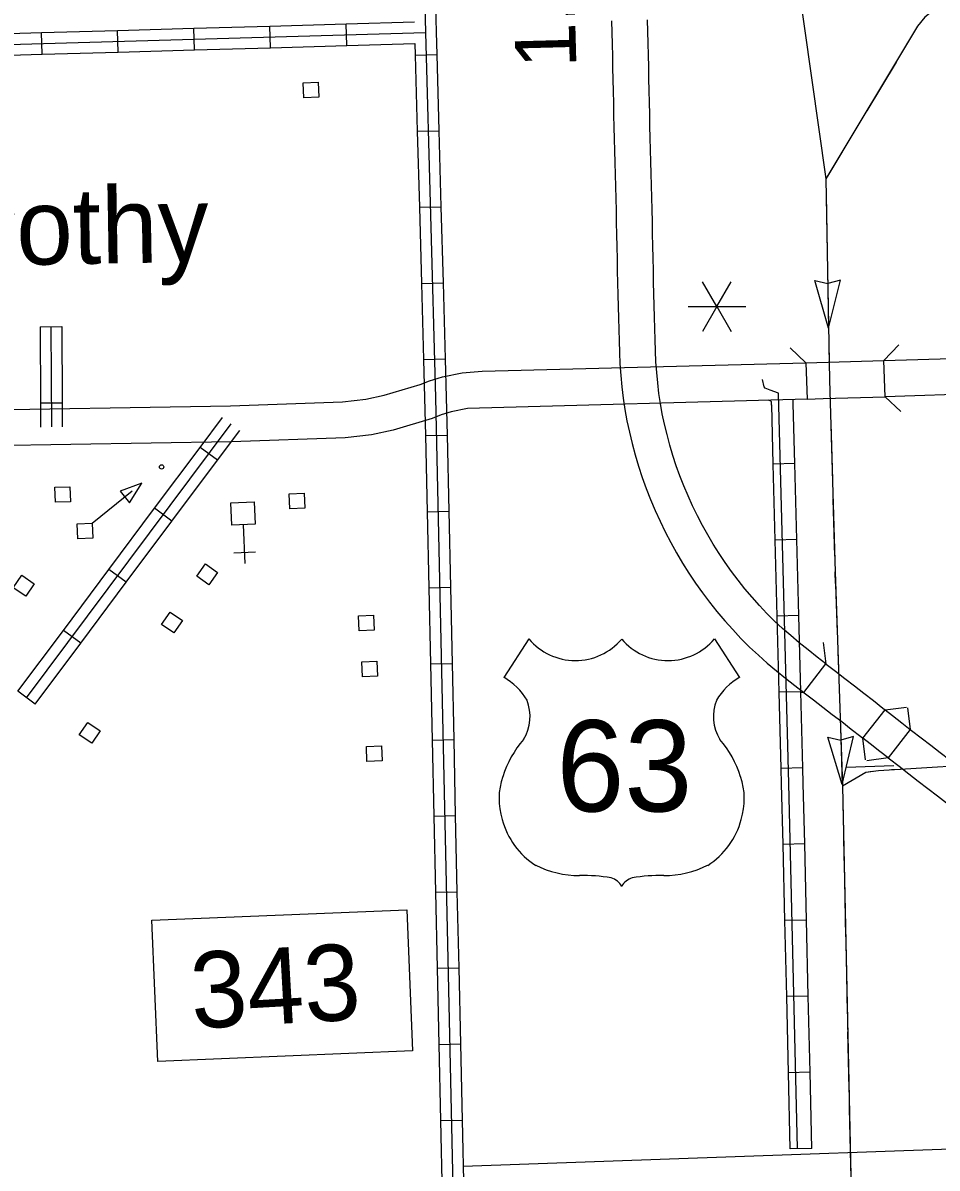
# Model space of a CAD drawing. Extents: x 1671357 to 13005564, y 567358 to 14261451.
# Drawn here: x 12758262.26 to 12758274.26, y 14259885.6 to 14259900.64 of the extents above; entities that cross this region are included whole.
import ezdxf

# ---------------------------------------------------------------- set-up
doc = ezdxf.new("R2010")
doc.units = 0
for name, color, linetype in [('10', 7, 'Continuous'), ('15', 7, 'Continuous'), ('22', 7, 'Continuous'), ('24', 7, 'Continuous'), ('32', 7, 'Continuous'), ('35', 7, 'Continuous'), ('37', 7, 'Continuous'), ('43', 7, 'Continuous'), ('48', 7, 'Continuous'), ('5', 7, 'Continuous'), ('56', 7, 'Continuous'), ('6', 7, 'Continuous'), ('60', 7, 'Continuous')]:
    doc.layers.add(name, color=color, linetype=linetype)

msp = doc.modelspace()

# ---------------------------------------------------------------- linework, layer by layer
at = {"layer": '10'}
msp.add_line((12758273.563, 14259896.205), (12758276.117, 14259896.288), dxfattribs=at)
msp.add_lwpolyline([(12758252.103, 14259895.45), (12758257.601, 14259895.49), (12758264.985, 14259895.609), (12758266.455, 14259895.665), (12758266.759, 14259895.697), (12758266.999, 14259895.749), (12758267.474, 14259895.892), (12758267.595, 14259895.941), (12758267.766, 14259895.99), (12758268.026, 14259896.045), (12758268.289, 14259896.068), (12758272.536, 14259896.175), (12758272.553, 14259895.7), (12758268.096, 14259895.575), (12758267.879, 14259895.53), (12758267.75, 14259895.493), (12758267.633, 14259895.445), (12758267.117, 14259895.291), (12758266.835, 14259895.229), (12758266.49, 14259895.192), (12758264.998, 14259895.136), (12758257.606, 14259895.017), (12758252.112, 14259894.977)], close=True, dxfattribs=at)
for points in [[(12758272.539, 14259896.175), (12758273.563, 14259896.205)], [(12758276.286, 14259895.828), (12758276.18, 14259895.817), (12758273.578, 14259895.731), (12758273.563, 14259896.205)], [(12758272.553, 14259895.7), (12758272.763, 14259895.705), (12758273.578, 14259895.731)]]:
    msp.add_lwpolyline(points, dxfattribs=at)
at = {"layer": '15'}
for p, q in [((12758272.513, 14259891.845), (12758272.802, 14259892.22)), ((12758273.287, 14259891.244), (12758273.579, 14259891.616)), ((12758273.909, 14259891.359), (12758273.62, 14259890.984))]:
    msp.add_line(p, q, dxfattribs=at)
for points in [[(12758269.985, 14259900.671), (12758269.989, 14259900.516), (12758269.993, 14259900.361), (12758269.997, 14259900.207)], [(12758270.471, 14259900.219), (12758270.467, 14259900.374), (12758270.462, 14259900.529), (12758270.458, 14259900.684)], [(12758269.997, 14259900.208), (12758270.001, 14259900.053), (12758270.004, 14259899.899), (12758270.007, 14259899.743), (12758270.011, 14259899.587), (12758270.014, 14259899.431), (12758270.018, 14259899.274), (12758270.022, 14259899.118), (12758270.026, 14259898.962), (12758270.031, 14259898.806), (12758270.035, 14259898.649), (12758270.039, 14259898.493), (12758270.042, 14259898.337), (12758270.045, 14259898.179), (12758270.049, 14259898.02), (12758270.053, 14259897.861), (12758270.056, 14259897.701), (12758270.059, 14259897.542), (12758270.062, 14259897.384), (12758270.066, 14259897.226), (12758270.069, 14259897.07), (12758270.072, 14259896.916), (12758270.076, 14259896.764), (12758270.08, 14259896.613), (12758270.085, 14259896.463), (12758270.091, 14259896.313), (12758270.097, 14259896.162), (12758270.108, 14259896.011), (12758270.122, 14259895.861), (12758270.14, 14259895.712), (12758270.161, 14259895.563), (12758270.189, 14259895.414), (12758270.221, 14259895.266), (12758270.256, 14259895.117), (12758270.296, 14259894.967), (12758270.34, 14259894.818), (12758270.388, 14259894.67), (12758270.441, 14259894.523), (12758270.498, 14259894.378), (12758270.558, 14259894.235), (12758270.623, 14259894.094), (12758270.691, 14259893.954), (12758270.763, 14259893.816), (12758270.839, 14259893.679), (12758270.918, 14259893.545), (12758271.001, 14259893.412), (12758271.088, 14259893.282), (12758271.179, 14259893.155), (12758271.274, 14259893.03), (12758271.371, 14259892.908), (12758271.473, 14259892.787), (12758271.577, 14259892.67), (12758271.686, 14259892.555), (12758271.798, 14259892.442), (12758271.914, 14259892.334), (12758272.031, 14259892.231), (12758272.151, 14259892.131), (12758272.272, 14259892.033), (12758272.394, 14259891.937), (12758272.513, 14259891.845)], [(12758272.802, 14259892.22), (12758272.685, 14259892.31), (12758272.567, 14259892.403), (12758272.452, 14259892.496), (12758272.34, 14259892.591), (12758272.231, 14259892.686), (12758272.127, 14259892.783), (12758272.026, 14259892.884), (12758271.927, 14259892.989), (12758271.831, 14259893.097), (12758271.738, 14259893.208), (12758271.648, 14259893.321), (12758271.561, 14259893.435), (12758271.478, 14259893.552), (12758271.398, 14259893.67), (12758271.322, 14259893.791), (12758271.25, 14259893.914), (12758271.18, 14259894.04), (12758271.114, 14259894.167), (12758271.051, 14259894.296), (12758270.992, 14259894.427), (12758270.936, 14259894.558), (12758270.884, 14259894.69), (12758270.836, 14259894.823), (12758270.792, 14259894.959), (12758270.752, 14259895.095), (12758270.715, 14259895.232), (12758270.682, 14259895.37), (12758270.653, 14259895.506), (12758270.629, 14259895.64), (12758270.609, 14259895.774), (12758270.593, 14259895.911), (12758270.58, 14259896.05), (12758270.57, 14259896.189), (12758270.564, 14259896.332), (12758270.558, 14259896.478), (12758270.554, 14259896.627), (12758270.55, 14259896.776), (12758270.546, 14259896.927), (12758270.542, 14259897.081), (12758270.539, 14259897.236), (12758270.536, 14259897.393), (12758270.532, 14259897.552), (12758270.529, 14259897.711), (12758270.526, 14259897.871), (12758270.523, 14259898.03), (12758270.519, 14259898.189), (12758270.516, 14259898.347), (12758270.512, 14259898.505), (12758270.508, 14259898.662), (12758270.504, 14259898.818), (12758270.5, 14259898.975), (12758270.495, 14259899.131), (12758270.491, 14259899.286), (12758270.488, 14259899.441), (12758270.484, 14259899.597), (12758270.481, 14259899.753), (12758270.478, 14259899.909), (12758270.474, 14259900.064), (12758270.471, 14259900.219)], [(12758272.802, 14259892.22), (12758272.805, 14259892.217), (12758272.928, 14259892.123), (12758273.051, 14259892.027), (12758273.175, 14259891.931), (12758273.3, 14259891.834), (12758273.426, 14259891.737), (12758273.55, 14259891.639), (12758273.579, 14259891.616)], [(12758272.513, 14259891.845), (12758272.516, 14259891.842), (12758272.639, 14259891.748), (12758272.762, 14259891.653), (12758272.885, 14259891.557), (12758273.009, 14259891.461), (12758273.134, 14259891.364), (12758273.258, 14259891.266), (12758273.287, 14259891.244)], [(12758273.579, 14259891.616), (12758273.675, 14259891.541), (12758273.8, 14259891.444), (12758273.909, 14259891.359)], [(12758273.909, 14259891.359), (12758273.925, 14259891.347), (12758274.052, 14259891.249), (12758274.178, 14259891.152), (12758274.303, 14259891.055), (12758274.429, 14259890.958), (12758274.555, 14259890.861), (12758274.674, 14259890.769)], [(12758273.62, 14259890.984), (12758273.509, 14259891.07), (12758273.383, 14259891.168), (12758273.287, 14259891.244)], [(12758273.62, 14259890.984), (12758273.636, 14259890.972), (12758273.762, 14259890.875), (12758273.888, 14259890.777), (12758274.014, 14259890.679), (12758274.14, 14259890.582), (12758274.266, 14259890.486), (12758274.385, 14259890.394)]]:
    msp.add_lwpolyline(points, dxfattribs=at)
at = {"layer": '22'}
for p, q in [((12758268.901, 14259892.549), (12758268.573, 14259892.042)), ((12758271.339, 14259892.549), (12758271.666, 14259892.042))]:
    msp.add_line(p, q, dxfattribs=at)
for centre, radius, start, end in [((12758269.511, 14259893.062), 0.798, 220.075, 319.6701), ((12758270.728, 14259893.062), 0.798, 220.3299, 319.925), ((12758268.145, 14259891.306), 0.852, 30.7809, 59.9883), ((12758272.095, 14259891.306), 0.852, 120.0117, 149.2191), ((12758268.332, 14259891.53), 0.584, 328.8105, 21.2108), ((12758271.907, 14259891.53), 0.584, 158.7892, 211.1895), ((12758269.859, 14259890.333), 1.362, 138.9565, 162.6913), ((12758270.38, 14259890.333), 1.362, 17.3087, 41.0435), ((12758269.409, 14259890.445), 0.9, 160.9576, 197.3819), ((12758270.83, 14259890.445), 0.9, 342.6181, 19.0424), ((12758269.556, 14259890.448), 1.042, 195.1074, 237.1312), ((12758270.684, 14259890.448), 1.042, 302.8688, 344.8926), ((12758269.575, 14259890.776), 1.337, 244.0771, 269.5779), ((12758270.664, 14259890.776), 1.337, 270.4221, 295.9229), ((12758269.606, 14259886.989), 2.45, 81.1942, 90.9539), ((12758269.913, 14259889.185), 0.235, 28.0342, 72.9864), ((12758270.327, 14259889.185), 0.235, 107.0136, 151.9658), ((12758270.633, 14259886.989), 2.45, 89.0461, 98.8058)]:
    msp.add_arc(centre, radius, start, end, dxfattribs=at)
at = {"layer": '32'}
for p, q in [((12758262.51, 14259900.231), (12758262.502, 14259900.515)), ((12758263.509, 14259900.259), (12758263.501, 14259900.543)), ((12758264.509, 14259900.288), (12758264.501, 14259900.572)), ((12758265.509, 14259900.316), (12758265.501, 14259900.6)), ((12758266.509, 14259900.345), (12758266.5, 14259900.629)), ((12758267.408, 14259900.218), (12758267.692, 14259900.226)), ((12758267.435, 14259899.218), (12758267.719, 14259899.226)), ((12758267.463, 14259898.219), (12758267.747, 14259898.226)), ((12758267.49, 14259897.219), (12758267.774, 14259897.227)), ((12758262.483, 14259896.65), (12758262.767, 14259896.651)), ((12758267.517, 14259896.219), (12758267.801, 14259896.227)), ((12758262.489, 14259895.65), (12758262.773, 14259895.651)), ((12758267.542, 14259895.22), (12758267.826, 14259895.226)), ((12758264.812, 14259894.895), (12758264.584, 14259895.065)), ((12758272.393, 14259894.854), (12758272.109, 14259894.846)), ((12758264.213, 14259894.094), (12758263.986, 14259894.264)), ((12758267.564, 14259894.22), (12758267.848, 14259894.226)), ((12758272.42, 14259893.854), (12758272.136, 14259893.846)), ((12758263.615, 14259893.292), (12758263.387, 14259893.462)), ((12758267.586, 14259893.22), (12758267.87, 14259893.226)), ((12758272.446, 14259892.854), (12758272.162, 14259892.847)), ((12758263.017, 14259892.491), (12758262.789, 14259892.661)), ((12758267.607, 14259892.22), (12758267.892, 14259892.227)), ((12758262.418, 14259891.69), (12758262.191, 14259891.86)), ((12758272.472, 14259891.854), (12758272.188, 14259891.847)), ((12758267.629, 14259891.22), (12758267.914, 14259891.227)), ((12758272.499, 14259890.855), (12758272.215, 14259890.847)), ((12758267.651, 14259890.221), (12758267.935, 14259890.227)), ((12758272.523, 14259889.854), (12758272.239, 14259889.848)), ((12758267.673, 14259889.221), (12758267.957, 14259889.227)), ((12758272.547, 14259888.854), (12758272.263, 14259888.848)), ((12758267.695, 14259888.221), (12758267.979, 14259888.227)), ((12758272.57, 14259887.855), (12758272.286, 14259887.848)), ((12758267.717, 14259887.221), (12758268.001, 14259887.227)), ((12758272.594, 14259886.855), (12758272.31, 14259886.848)), ((12758267.739, 14259886.221), (12758268.023, 14259886.227)), ((12758272.617, 14259885.855), (12758272.333, 14259885.848))]:
    msp.add_line(p, q, dxfattribs=at)
for points in [[(12758267.288, 14259909.193), (12758267.414, 14259905.851), (12758267.542, 14259900.517), (12758267.673, 14259895.717), (12758268.01, 14259880.366), (12758268.077, 14259880.309), (12758268.233, 14259880.297), (12758271.521, 14259880.629), (12758271.944, 14259880.629), (12758273.2, 14259880.673), (12758277.616, 14259880.857), (12758278.42, 14259880.876), (12758279.182, 14259880.918), (12758280.012, 14259880.961), (12758281.634, 14259881.05), (12758282.293, 14259881.066), (12758282.979, 14259881.061), (12758283.543, 14259881.078), (12758284.212, 14259881.201)], [(12758267.667, 14259901.225), (12758267.684, 14259900.521), (12758267.692, 14259900.226)], [(12758257.507, 14259900.229), (12758267.542, 14259900.517)], [(12758261.502, 14259900.486), (12758262.502, 14259900.515)], [(12758262.502, 14259900.515), (12758263.501, 14259900.543)], [(12758263.501, 14259900.543), (12758264.501, 14259900.572)], [(12758264.501, 14259900.572), (12758265.501, 14259900.6)], [(12758265.501, 14259900.6), (12758266.5, 14259900.629)], [(12758266.5, 14259900.629), (12758267.397, 14259900.655)], [(12758266.509, 14259900.345), (12758267.404, 14259900.371)], [(12758267.404, 14259900.371), (12758267.408, 14259900.218)], [(12758261.51, 14259900.202), (12758262.51, 14259900.231)], [(12758262.51, 14259900.231), (12758263.509, 14259900.259)], [(12758263.509, 14259900.259), (12758264.509, 14259900.288)], [(12758264.509, 14259900.288), (12758265.509, 14259900.316)], [(12758265.509, 14259900.316), (12758266.509, 14259900.345)], [(12758267.408, 14259900.218), (12758267.435, 14259899.218)], [(12758267.692, 14259900.226), (12758267.719, 14259899.226)], [(12758267.435, 14259899.218), (12758267.463, 14259898.219)], [(12758267.719, 14259899.226), (12758267.747, 14259898.226)], [(12758267.463, 14259898.219), (12758267.49, 14259897.219)], [(12758267.747, 14259898.226), (12758267.774, 14259897.227)], [(12758267.49, 14259897.219), (12758267.517, 14259896.219)], [(12758267.774, 14259897.227), (12758267.801, 14259896.227)], [(12758262.483, 14259896.65), (12758262.489, 14259895.65)], [(12758262.625, 14259896.65), (12758262.632, 14259895.333)], [(12758262.767, 14259896.651), (12758262.773, 14259895.651)], [(12758267.517, 14259896.219), (12758267.531, 14259895.714), (12758267.542, 14259895.22)], [(12758267.801, 14259896.227), (12758267.815, 14259895.721), (12758267.826, 14259895.226)], [(12758272.426, 14259885.854), (12758272.313, 14259890.648), (12758272.178, 14259895.777), (12758272.068, 14259895.817), (12758272.005, 14259895.845), (12758271.991, 14259895.86), (12758271.97, 14259895.956)], [(12758262.489, 14259895.65), (12758262.49, 14259895.332)], [(12758262.773, 14259895.651), (12758262.774, 14259895.334)], [(12758272.086, 14259895.668), (12758272.047, 14259895.685)], [(12758272.087, 14259895.62), (12758272.086, 14259895.668)], [(12758272.109, 14259894.846), (12758272.089, 14259895.625)], [(12758272.373, 14259895.638), (12758272.372, 14259895.69)], [(12758272.393, 14259894.854), (12758272.373, 14259895.639)], [(12758264.584, 14259895.065), (12758264.877, 14259895.458)], [(12758262.304, 14259891.775), (12758264.991, 14259895.373)], [(12758264.812, 14259894.895), (12758265.105, 14259895.288)], [(12758267.542, 14259895.22), (12758267.564, 14259894.22)], [(12758267.826, 14259895.226), (12758267.848, 14259894.226)], [(12758263.986, 14259894.264), (12758264.584, 14259895.065)], [(12758264.213, 14259894.094), (12758264.812, 14259894.895)], [(12758272.136, 14259893.846), (12758272.109, 14259894.846)], [(12758272.42, 14259893.854), (12758272.393, 14259894.854)], [(12758263.387, 14259893.462), (12758263.986, 14259894.264)], [(12758267.564, 14259894.22), (12758267.586, 14259893.22)], [(12758267.848, 14259894.226), (12758267.87, 14259893.226)], [(12758263.615, 14259893.292), (12758264.213, 14259894.094)], [(12758272.162, 14259892.847), (12758272.136, 14259893.846)], [(12758272.446, 14259892.854), (12758272.42, 14259893.854)], [(12758262.789, 14259892.661), (12758263.387, 14259893.462)], [(12758263.017, 14259892.491), (12758263.615, 14259893.292)], [(12758267.586, 14259893.22), (12758267.607, 14259892.22)], [(12758267.87, 14259893.226), (12758267.892, 14259892.227)], [(12758272.188, 14259891.847), (12758272.162, 14259892.847)], [(12758272.472, 14259891.854), (12758272.446, 14259892.854)], [(12758262.191, 14259891.86), (12758262.789, 14259892.661)], [(12758262.418, 14259891.69), (12758263.017, 14259892.491)], [(12758267.607, 14259892.22), (12758267.629, 14259891.22)], [(12758267.892, 14259892.227), (12758267.914, 14259891.227)], [(12758272.215, 14259890.847), (12758272.188, 14259891.847)], [(12758272.499, 14259890.855), (12758272.472, 14259891.854)], [(12758267.629, 14259891.22), (12758267.651, 14259890.221)], [(12758267.914, 14259891.227), (12758267.935, 14259890.227)], [(12758272.239, 14259889.848), (12758272.22, 14259890.643), (12758272.215, 14259890.847)], [(12758272.523, 14259889.854), (12758272.504, 14259890.65), (12758272.499, 14259890.855)], [(12758267.651, 14259890.221), (12758267.673, 14259889.221)], [(12758267.935, 14259890.227), (12758267.957, 14259889.227)], [(12758272.263, 14259888.848), (12758272.239, 14259889.848)], [(12758272.547, 14259888.854), (12758272.523, 14259889.854)], [(12758267.957, 14259889.227), (12758267.979, 14259888.227)], [(12758267.673, 14259889.221), (12758267.695, 14259888.221)], [(12758272.286, 14259887.848), (12758272.263, 14259888.848)], [(12758272.57, 14259887.855), (12758272.547, 14259888.854)], [(12758267.695, 14259888.221), (12758267.717, 14259887.221)], [(12758267.979, 14259888.227), (12758268.001, 14259887.227)], [(12758272.31, 14259886.848), (12758272.286, 14259887.848)], [(12758272.594, 14259886.855), (12758272.57, 14259887.855)], [(12758267.717, 14259887.221), (12758267.739, 14259886.221)], [(12758268.001, 14259887.227), (12758268.023, 14259886.227)], [(12758272.333, 14259885.848), (12758272.31, 14259886.848)], [(12758272.617, 14259885.855), (12758272.594, 14259886.855)], [(12758267.739, 14259886.221), (12758267.761, 14259885.221)], [(12758268.023, 14259886.227), (12758268.045, 14259885.227)]]:
    msp.add_lwpolyline(points, dxfattribs=at)
at = {"layer": '35'}
for points in [[(12758274.965, 14259901.018), (12758274.58, 14259900.927), (12758274.293, 14259900.832), (12758274.185, 14259900.783), (12758274.099, 14259900.717), (12758274.003, 14259900.601), (12758272.802, 14259898.593)], [(12758272.802, 14259898.593), (12758272.849, 14259895.95), (12758272.922, 14259893.429), (12758273.017, 14259890.615), (12758273.176, 14259883.241), (12758273.139, 14259882.897), (12758272.96, 14259882.398), (12758272.863, 14259882.216), (12758269.17, 14259876.344), (12758268.93, 14259876.062), (12758268.737, 14259875.922), (12758268.514, 14259875.793), (12758268.328, 14259875.705), (12758266.458, 14259875.091), (12758266.017, 14259874.983), (12758263.985, 14259874.814), (12758263.423, 14259874.758), (12758263.214, 14259874.724), (12758263.048, 14259874.668), (12758262.636, 14259874.462), (12758262.186, 14259874.219), (12758258.133, 14259871.914)]]:
    msp.add_lwpolyline(points, dxfattribs=at)
at = {"layer": '37'}
msp.add_line((12758273.571, 14259895.968), (12758273.571, 14259895.968), dxfattribs=at)
for points in [[(12758272.536, 14259896.175), (12758272.33, 14259896.371)], [(12758273.758, 14259896.412), (12758273.563, 14259896.205)], [(12758273.578, 14259895.731), (12758273.786, 14259895.537)], [(12758272.766, 14259892.501), (12758272.802, 14259892.22)], [(12758272.513, 14259891.845), (12758272.473, 14259891.838)], [(12758273.579, 14259891.616), (12758273.861, 14259891.651)], [(12758273.873, 14259891.641), (12758273.909, 14259891.359)], [(12758273.321, 14259890.961), (12758273.287, 14259891.244)], [(12758273.62, 14259890.984), (12758273.338, 14259890.948)]]:
    msp.add_lwpolyline(points, dxfattribs=at)
at = {"layer": '43'}
for p, q in [((12758272.837, 14259896.633), (12758272.657, 14259897.258)), ((12758272.657, 14259897.258), (12758272.825, 14259897.216)), ((12758272.994, 14259897.264), (12758272.828, 14259897.216)), ((12758272.837, 14259896.633), (12758272.994, 14259897.264)), ((12758273.016, 14259890.635), (12758272.827, 14259891.257)), ((12758272.827, 14259891.257), (12758272.996, 14259891.218)), ((12758273.163, 14259891.268), (12758272.998, 14259891.218)), ((12758273.016, 14259890.635), (12758273.163, 14259891.268))]:
    msp.add_line(p, q, dxfattribs=at)
for points in [[(12758274.965, 14259901.018), (12758274.712, 14259900.954), (12758274.58, 14259900.927), (12758274.403, 14259900.867), (12758274.293, 14259900.832), (12758274.185, 14259900.783), (12758274.099, 14259900.717), (12758274.003, 14259900.601), (12758273.887, 14259900.402), (12758272.802, 14259898.593)], [(12758274.242, 14259900.809), (12758274.185, 14259900.783), (12758274.099, 14259900.717), (12758274.003, 14259900.601), (12758273.887, 14259900.402), (12758273.851, 14259900.343)], [(12758273.723, 14259900.128), (12758273.337, 14259899.485)], [(12758273.209, 14259899.27), (12758272.823, 14259898.627)], [(12758272.802, 14259898.593), (12758272.849, 14259895.95), (12758272.922, 14259893.429), (12758273.017, 14259890.615), (12758273.158, 14259884.008)], [(12758272.806, 14259898.383), (12758272.819, 14259897.633)], [(12758272.823, 14259897.383), (12758272.837, 14259896.633)], [(12758272.841, 14259896.383), (12758272.844, 14259896.184)], [(12758272.856, 14259895.708), (12758272.858, 14259895.633)], [(12758272.865, 14259895.383), (12758272.887, 14259894.633)], [(12758272.894, 14259894.383), (12758272.916, 14259893.634)], [(12758272.923, 14259893.384), (12758272.949, 14259892.634)], [(12758272.957, 14259892.384), (12758272.965, 14259892.147)], [(12758272.991, 14259891.384), (12758273.016, 14259890.635)], [(12758278.831, 14259891.346), (12758278.803, 14259891.34), (12758275.445, 14259890.903), (12758274.622, 14259890.885), (12758273.492, 14259890.816), (12758273.324, 14259890.792), (12758273.017, 14259890.615)], [(12758273.412, 14259890.805), (12758273.324, 14259890.792), (12758273.017, 14259890.615)], [(12758273.781, 14259890.834), (12758273.661, 14259890.827)], [(12758273.022, 14259890.385), (12758273.03, 14259890.01)], [(12758273.03, 14259890.01), (12758273.038, 14259889.635)], [(12758273.043, 14259889.385), (12758273.059, 14259888.635)], [(12758273.065, 14259888.385), (12758273.081, 14259887.635)], [(12758273.086, 14259887.385), (12758273.102, 14259886.635)], [(12758273.107, 14259886.385), (12758273.123, 14259885.635)]]:
    msp.add_lwpolyline(points, dxfattribs=at)
at = {"layer": '48'}
for p, q in [((12758271.37, 14259896.914), (12758271.18, 14259897.242)), ((12758271.37, 14259896.914), (12758271.559, 14259897.242)), ((12758270.991, 14259896.914), (12758271.37, 14259896.914)), ((12758271.37, 14259896.914), (12758271.18, 14259896.586)), ((12758271.37, 14259896.914), (12758271.748, 14259896.914)), ((12758271.37, 14259896.914), (12758271.559, 14259896.586))]:
    msp.add_line(p, q, dxfattribs=at)
at = {"layer": '5'}
msp.add_lwpolyline([(12758277.891, 14259885.965), (12758268.037, 14259885.616)], dxfattribs=at)
at = {"layer": '56'}
for p, q in [((12758263.168, 14259894.067), (12758263.694, 14259894.494)), ((12758265.174, 14259893.539), (12758265.153, 14259894.049)), ((12758265.31, 14259893.687), (12758265.026, 14259893.675))]:
    msp.add_line(p, q, dxfattribs=at)
for points in [[(12758265.947, 14259899.659), (12758265.938, 14259899.856), (12758266.136, 14259899.864), (12758266.144, 14259899.667)], [(12758262.685, 14259894.343), (12758262.677, 14259894.54), (12758262.875, 14259894.548), (12758262.883, 14259894.351)], [(12758263.535, 14259894.488), (12758263.657, 14259894.338), (12758263.821, 14259894.596)], [(12758265.294, 14259894.351), (12758265.306, 14259894.055), (12758265, 14259894.042), (12758264.987, 14259894.338)], [(12758265.761, 14259894.258), (12758265.752, 14259894.455), (12758265.95, 14259894.463), (12758265.958, 14259894.266)], [(12758262.979, 14259893.862), (12758262.971, 14259894.059), (12758263.168, 14259894.067), (12758263.177, 14259893.87)], [(12758264.7, 14259893.259), (12758264.539, 14259893.373), (12758264.654, 14259893.534), (12758264.814, 14259893.42)], [(12758262.294, 14259893.109), (12758262.131, 14259893.22), (12758262.243, 14259893.384), (12758262.406, 14259893.273)], [(12758264.241, 14259892.626), (12758264.078, 14259892.737), (12758264.189, 14259892.9), (12758264.352, 14259892.79)], [(12758266.672, 14259892.655), (12758266.663, 14259892.852), (12758266.861, 14259892.86), (12758266.869, 14259892.663)], [(12758266.717, 14259892.051), (12758266.709, 14259892.248), (12758266.906, 14259892.256), (12758266.915, 14259892.059)], [(12758263.162, 14259891.178), (12758262.998, 14259891.289), (12758263.109, 14259891.452), (12758263.273, 14259891.342)], [(12758266.775, 14259890.939), (12758266.767, 14259891.136), (12758266.964, 14259891.144), (12758266.973, 14259890.947)]]:
    msp.add_lwpolyline(points, close=True, dxfattribs=at)
msp.add_circle((12758264.078, 14259894.808), 0.0284, dxfattribs=at)
at = {"layer": '6'}
for points in [[(12758272.236, 14259902.58), (12758272.802, 14259898.593)], [(12758272.927, 14259893.277), (12758272.922, 14259893.429)], [(12758273.691, 14259890.88), (12758273.068, 14259890.858)]]:
    msp.add_lwpolyline(points, dxfattribs=at)
at = {"layer": '60'}
msp.add_lwpolyline([(12758263.951, 14259888.852), (12758267.297, 14259888.99), (12758267.374, 14259887.135), (12758264.027, 14259886.997)], close=True, dxfattribs=at)

# ---------------------------------------------------------------- texts
at = {"layer": '22'}
msp.add_text('63', height=1.199, dxfattribs=at).set_placement((12758269.263, 14259890.281))
at = {"layer": '24'}
msp.add_text('Dorothy', height=1.0001, rotation=0.926, dxfattribs=at).set_placement((12758260.021, 14259897.427))
at = {"layer": '48'}
msp.add_text('1.5', height=0.8001, rotation=91.5526, dxfattribs=at).set_placement((12758269.526, 14259900.058))
at = {"layer": '60'}
msp.add_text('343', height=1, rotation=3.2397, dxfattribs=at).set_placement((12758264.484, 14259887.426))

doc.saveas('drawing.dxf')
